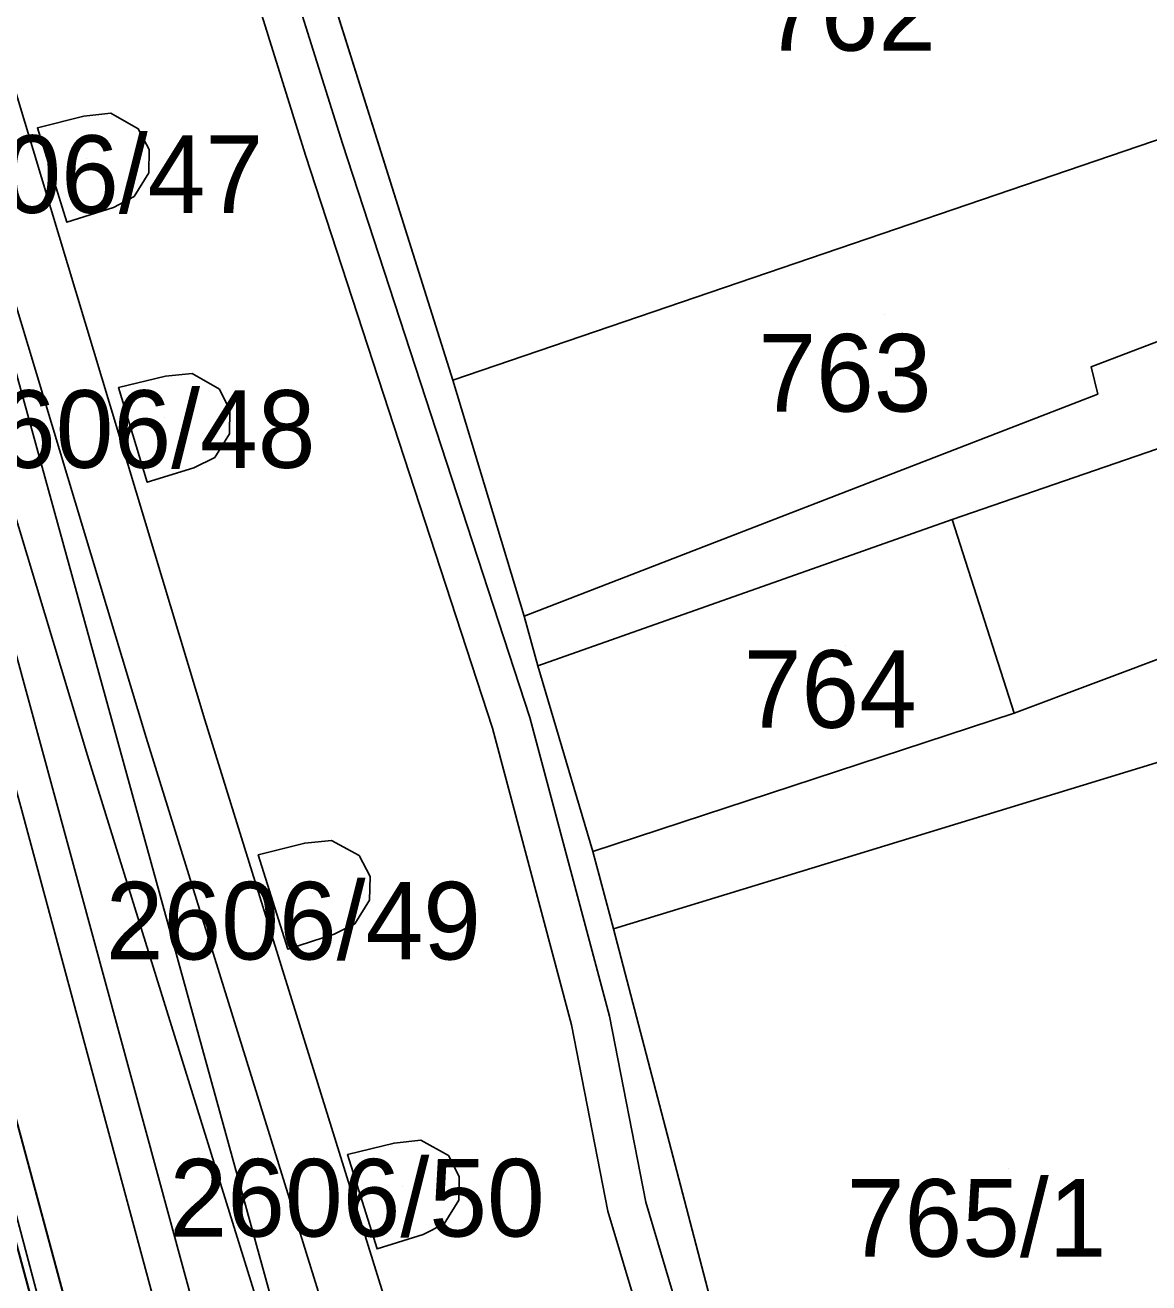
# Model space of a CAD drawing. Extents: x -263423 to -261326, y -1240067 to -1237864.
# Drawn here: x -262913.52 to -262884.56, y -1239127.34 to -1239094.93 of the extents above; entities that cross this region are included whole.
import ezdxf

# ---------------------------------------------------------------- set-up
doc = ezdxf.new("R2010")
doc.units = 0
for name, color, linetype in [('body_kn', 7, 'Continuous'), ('kladpar_druhypozemkov', 7, 'Continuous'), ('kladpar_hranice', 7, 'Continuous'), ('kladpar_parcelnecisla', 7, 'Continuous'), ('kladpar_plochy', 7, 'Continuous'), ('tarchy_linie', 7, 'Continuous'), ('zappar_hrandruhpozemk', 7, 'Continuous')]:
    doc.layers.add(name, color=color, linetype=linetype)

msp = doc.modelspace()

# ---------------------------------------------------------------- linework, layer by layer
at = {"layer": 'body_kn'}
for p, q in [((-262912, -1239097.28), (-262912, -1239097.28)), ((-262911.31, -1239097.2), (-262911.31, -1239097.2)), ((-262913.2, -1239097.58), (-262913.2, -1239097.58)), ((-262913.2, -1239097.58), (-262913.2, -1239097.58)), ((-262910.6, -1239097.6), (-262910.6, -1239097.6)), ((-262910.32, -1239098.14), (-262910.32, -1239098.14)), ((-262906.29, -1239098.28), (-262906.29, -1239098.28)), ((-262905.34, -1239097.98), (-262905.34, -1239097.98)), ((-262910.33, -1239098.74), (-262910.33, -1239098.74)), ((-262910.71, -1239099.35), (-262910.71, -1239099.35)), ((-262911.24, -1239099.63), (-262911.24, -1239099.63)), ((-262912.44, -1239100.01), (-262912.44, -1239100.01)), ((-262886.05, -1239103.74), (-262886.05, -1239103.74)), ((-262909.9, -1239103.98), (-262909.9, -1239103.98)), ((-262909.21, -1239103.91), (-262909.21, -1239103.91)), ((-262902.5, -1239104.08), (-262902.5, -1239104.08)), ((-262911.11, -1239104.27), (-262911.11, -1239104.27)), ((-262911.11, -1239104.27), (-262911.11, -1239104.27)), ((-262908.51, -1239104.31), (-262908.51, -1239104.31)), ((-262885.88, -1239104.44), (-262885.88, -1239104.44)), ((-262908.24, -1239104.85), (-262908.24, -1239104.85)), ((-262908.25, -1239105.46), (-262908.25, -1239105.46)), ((-262909.17, -1239106.34), (-262909.17, -1239106.34)), ((-262908.63, -1239106.07), (-262908.63, -1239106.07)), ((-262910.37, -1239106.71), (-262910.37, -1239106.71)), ((-262889.63, -1239107.67), (-262889.63, -1239107.67)), ((-262900.66, -1239110.16), (-262900.66, -1239110.16)), ((-262900.31, -1239111.44), (-262900.31, -1239111.44)), ((-262908.89, -1239112.83), (-262908.89, -1239112.83)), ((-262900.51, -1239112.77), (-262900.51, -1239112.77)), ((-262888.03, -1239112.66), (-262888.03, -1239112.66)), ((-262888.03, -1239112.66), (-262888.03, -1239112.66)), ((-262901.47, -1239113.05), (-262901.47, -1239113.05)), ((-262910.4, -1239113.29), (-262910.4, -1239113.29)), ((-262911.91, -1239113.75), (-262911.91, -1239113.75)), ((-262906.31, -1239116.01), (-262906.31, -1239116.01)), ((-262905.62, -1239115.94), (-262905.62, -1239115.94)), ((-262907.51, -1239116.31), (-262907.51, -1239116.31)), ((-262907.51, -1239116.31), (-262907.51, -1239116.31)), ((-262904.91, -1239116.33), (-262904.91, -1239116.33)), ((-262898.89, -1239116.23), (-262898.89, -1239116.23)), ((-262898.89, -1239116.23), (-262898.89, -1239116.23)), ((-262904.63, -1239116.87), (-262904.63, -1239116.87)), ((-262904.64, -1239117.48), (-262904.64, -1239117.48)), ((-262905.55, -1239118.36), (-262905.55, -1239118.36)), ((-262905.02, -1239118.09), (-262905.02, -1239118.09)), ((-262898.36, -1239118.22), (-262898.36, -1239118.22)), ((-262906.75, -1239118.74), (-262906.75, -1239118.74)), ((-262898.46, -1239120.47), (-262898.46, -1239120.47)), ((-262899.44, -1239120.69), (-262899.44, -1239120.69)), ((-262904.01, -1239123.74), (-262904.01, -1239123.74)), ((-262903.32, -1239123.67), (-262903.32, -1239123.67)), ((-262905.21, -1239124.04), (-262905.21, -1239124.04)), ((-262905.21, -1239124.04), (-262905.21, -1239124.04)), ((-262902.61, -1239124.06), (-262902.61, -1239124.06)), ((-262902.33, -1239124.6), (-262902.33, -1239124.6)), ((-262902.34, -1239125.21), (-262902.34, -1239125.21)), ((-262898.5, -1239125.5), (-262898.5, -1239125.5)), ((-262897.52, -1239125.26), (-262897.52, -1239125.26)), ((-262902.72, -1239125.82), (-262902.72, -1239125.82)), ((-262903.26, -1239126.1), (-262903.26, -1239126.1)), ((-262904.45, -1239126.47), (-262904.45, -1239126.47))]:
    msp.add_line(p, q, dxfattribs=at)
at = {"layer": 'kladpar_druhypozemkov'}
for p, q in [((-262911.94, -1239098.36), (-262911.94, -1239098.36)), ((-262891.37, -1239102.39), (-262891.37, -1239102.39)), ((-262909.92, -1239105.03), (-262909.92, -1239105.03)), ((-262892.38, -1239110.93), (-262892.38, -1239110.93)), ((-262906.11, -1239117.31), (-262906.11, -1239117.31)), ((-262888.17, -1239124.39), (-262888.17, -1239124.39)), ((-262903.79, -1239124.87), (-262903.79, -1239124.87))]:
    msp.add_line(p, q, dxfattribs=at)
at = {"layer": 'kladpar_hranice'}
for points in [[(-262893.7, -1239198.54), (-262894.26, -1239197.51), (-262894.85, -1239196.01), (-262897, -1239188.23), (-262908.38, -1239146.15), (-262916.07, -1239117.75), (-262916.78, -1239116.26), (-262916.91, -1239114.53), (-262935.33, -1239046.71)], [(-262935.33, -1239046.71), (-262916.91, -1239114.53), (-262916.78, -1239116.26), (-262916.07, -1239117.75), (-262908.38, -1239146.15), (-262897, -1239188.23), (-262894.85, -1239196.01), (-262894.26, -1239197.51), (-262893.7, -1239198.54)], [(-262934.53, -1239046.57), (-262916.13, -1239114.22), (-262915.54, -1239115.96), (-262915.28, -1239117.47), (-262907.62, -1239145.83), (-262896.2, -1239187.94), (-262894.08, -1239195.84), (-262893.54, -1239197.19), (-262892.9, -1239198.44)], [(-262882.09, -1239085.08), (-262863.43, -1239079.26), (-262845.68, -1239073.99), (-262839.87, -1239072.34), (-262840.28, -1239070.93), (-262817.72, -1239063.42), (-262815.92, -1239068.28), (-262804.92, -1239064.46), (-262804.22, -1239064.15), (-262802.54, -1239068.64), (-262803.43, -1239068.94), (-262812.96, -1239072.03), (-262826.95, -1239076.56), (-262867.57, -1239091.24), (-262877.82, -1239095.66), (-262902.5, -1239104.08), (-262905.88, -1239093.33), (-262882.09, -1239085.08)], [(-262877.82, -1239095.66), (-262867.57, -1239091.24), (-262826.95, -1239076.56), (-262824.67, -1239082.26), (-262830.49, -1239084.62), (-262845.67, -1239091.15), (-262842.8, -1239099.09), (-262852.59, -1239102.56), (-262855.47, -1239095), (-262865.58, -1239099.04), (-262877.68, -1239103.86), (-262880.24, -1239104.88), (-262880.42, -1239104.5), (-262889.63, -1239107.67), (-262900.31, -1239111.44), (-262900.66, -1239110.16), (-262902.5, -1239104.08), (-262877.82, -1239095.66)], [(-262905.88, -1239093.33), (-262902.5, -1239104.08), (-262900.66, -1239110.16), (-262900.31, -1239111.44), (-262898.89, -1239116.23), (-262898.36, -1239118.22), (-262892.33, -1239141.29), (-262882.82, -1239170.53)], [(-262880.42, -1239104.5), (-262880.24, -1239104.88), (-262877.68, -1239103.86), (-262865.58, -1239099.04), (-262855.47, -1239095), (-262852.59, -1239102.56), (-262877.47, -1239111.62), (-262884.37, -1239113.94), (-262898.36, -1239118.22), (-262898.89, -1239116.23), (-262900.31, -1239111.44), (-262889.63, -1239107.67), (-262880.42, -1239104.5)], [(-262913.2, -1239097.58), (-262912, -1239097.28), (-262911.31, -1239097.2), (-262910.6, -1239097.6), (-262910.32, -1239098.14), (-262910.33, -1239098.74), (-262910.71, -1239099.35), (-262911.24, -1239099.63), (-262912.44, -1239100.01), (-262913.2, -1239097.58)], [(-262912, -1239097.28), (-262913.2, -1239097.58), (-262912.44, -1239100.01), (-262911.24, -1239099.63), (-262910.71, -1239099.35), (-262910.33, -1239098.74), (-262910.32, -1239098.14), (-262910.6, -1239097.6), (-262911.31, -1239097.2), (-262912, -1239097.28)], [(-262822.99, -1239113.06), (-262828.11, -1239114.91), (-262830.61, -1239115.81), (-262830.86, -1239115.87), (-262834.7, -1239117.31), (-262838.92, -1239118.87), (-262842.78, -1239109.77), (-262854.56, -1239114.01), (-262883.4, -1239124.39), (-262882.63, -1239126.82), (-262879.24, -1239125.88), (-262878.23, -1239129.07), (-262875.93, -1239128.36), (-262874.04, -1239134.82), (-262892.33, -1239141.29), (-262898.36, -1239118.22), (-262884.37, -1239113.94), (-262877.47, -1239111.62), (-262852.59, -1239102.56)], [(-262911.11, -1239104.27), (-262909.9, -1239103.98), (-262909.21, -1239103.91), (-262908.51, -1239104.31), (-262908.24, -1239104.85), (-262908.25, -1239105.46), (-262908.63, -1239106.07), (-262909.17, -1239106.34), (-262910.37, -1239106.71), (-262911.11, -1239104.27)], [(-262909.9, -1239103.98), (-262911.11, -1239104.27), (-262910.37, -1239106.71), (-262909.17, -1239106.34), (-262908.63, -1239106.07), (-262908.25, -1239105.46), (-262908.24, -1239104.85), (-262908.51, -1239104.31), (-262909.21, -1239103.91), (-262909.9, -1239103.98)], [(-262892.9, -1239198.44), (-262893.54, -1239197.19), (-262894.08, -1239195.84), (-262896.2, -1239187.94), (-262907.62, -1239145.83), (-262915.28, -1239117.47), (-262915.54, -1239115.96), (-262916.13, -1239114.22)], [(-262907.51, -1239116.31), (-262906.31, -1239116.01), (-262905.62, -1239115.94), (-262904.91, -1239116.33), (-262904.63, -1239116.87), (-262904.64, -1239117.48), (-262905.02, -1239118.09), (-262905.55, -1239118.36), (-262906.75, -1239118.74), (-262907.51, -1239116.31)], [(-262906.31, -1239116.01), (-262907.51, -1239116.31), (-262906.75, -1239118.74), (-262905.55, -1239118.36), (-262905.02, -1239118.09), (-262904.64, -1239117.48), (-262904.63, -1239116.87), (-262904.91, -1239116.33), (-262905.62, -1239115.94), (-262906.31, -1239116.01)], [(-262905.21, -1239124.04), (-262904.01, -1239123.74), (-262903.32, -1239123.67), (-262902.61, -1239124.06), (-262902.33, -1239124.6), (-262902.34, -1239125.21), (-262902.72, -1239125.82), (-262903.26, -1239126.1), (-262904.45, -1239126.47), (-262905.21, -1239124.04)], [(-262904.01, -1239123.74), (-262905.21, -1239124.04), (-262904.45, -1239126.47), (-262903.26, -1239126.1), (-262902.72, -1239125.82), (-262902.34, -1239125.21), (-262902.33, -1239124.6), (-262902.61, -1239124.06), (-262903.32, -1239123.67), (-262904.01, -1239123.74)]]:
    msp.add_lwpolyline(points, dxfattribs=at)
at = {"layer": 'kladpar_plochy'}
for p, q in [((-262905.88, -1239093.33), (-262902.5, -1239104.08)), ((-262912, -1239097.28), (-262913.2, -1239097.58)), ((-262911.31, -1239097.2), (-262912, -1239097.28)), ((-262910.6, -1239097.6), (-262911.31, -1239097.2)), ((-262913.2, -1239097.58), (-262912.44, -1239100.01)), ((-262910.32, -1239098.14), (-262910.6, -1239097.6)), ((-262910.33, -1239098.74), (-262910.32, -1239098.14)), ((-262910.71, -1239099.35), (-262910.33, -1239098.74)), ((-262911.24, -1239099.63), (-262910.71, -1239099.35)), ((-262912.44, -1239100.01), (-262911.24, -1239099.63)), ((-262909.9, -1239103.98), (-262911.11, -1239104.27)), ((-262909.21, -1239103.91), (-262909.9, -1239103.98)), ((-262908.51, -1239104.31), (-262909.21, -1239103.91)), ((-262902.5, -1239104.08), (-262900.66, -1239110.16)), ((-262911.11, -1239104.27), (-262910.37, -1239106.71)), ((-262908.24, -1239104.85), (-262908.51, -1239104.31)), ((-262908.25, -1239105.46), (-262908.24, -1239104.85)), ((-262908.63, -1239106.07), (-262908.25, -1239105.46)), ((-262910.37, -1239106.71), (-262909.17, -1239106.34)), ((-262909.17, -1239106.34), (-262908.63, -1239106.07)), ((-262900.66, -1239110.16), (-262900.31, -1239111.44)), ((-262900.31, -1239111.44), (-262898.89, -1239116.23)), ((-262906.31, -1239116.01), (-262907.51, -1239116.31)), ((-262905.62, -1239115.94), (-262906.31, -1239116.01)), ((-262904.91, -1239116.33), (-262905.62, -1239115.94)), ((-262907.51, -1239116.31), (-262906.75, -1239118.74)), ((-262904.63, -1239116.87), (-262904.91, -1239116.33)), ((-262898.89, -1239116.23), (-262898.36, -1239118.22)), ((-262904.64, -1239117.48), (-262904.63, -1239116.87)), ((-262907.62, -1239145.83), (-262915.28, -1239117.47)), ((-262905.02, -1239118.09), (-262904.64, -1239117.48)), ((-262916.07, -1239117.75), (-262908.38, -1239146.15)), ((-262906.75, -1239118.74), (-262905.55, -1239118.36)), ((-262905.55, -1239118.36), (-262905.02, -1239118.09)), ((-262898.36, -1239118.22), (-262892.33, -1239141.29)), ((-262904.01, -1239123.74), (-262905.21, -1239124.04)), ((-262903.32, -1239123.67), (-262904.01, -1239123.74)), ((-262902.61, -1239124.06), (-262903.32, -1239123.67)), ((-262905.21, -1239124.04), (-262904.45, -1239126.47)), ((-262902.33, -1239124.6), (-262902.61, -1239124.06)), ((-262902.34, -1239125.21), (-262902.33, -1239124.6)), ((-262902.72, -1239125.82), (-262902.34, -1239125.21)), ((-262903.26, -1239126.1), (-262902.72, -1239125.82)), ((-262904.45, -1239126.47), (-262903.26, -1239126.1))]:
    msp.add_line(p, q, dxfattribs=at)
for points in [[(-262893.7, -1239198.54), (-262894.26, -1239197.51), (-262894.85, -1239196.01), (-262897, -1239188.23), (-262908.38, -1239146.15), (-262916.07, -1239117.75), (-262916.78, -1239116.26), (-262916.91, -1239114.53), (-262935.33, -1239046.71)], [(-262934.53, -1239046.57), (-262916.13, -1239114.22), (-262915.54, -1239115.96), (-262915.28, -1239117.47), (-262907.62, -1239145.83), (-262896.2, -1239187.94), (-262894.08, -1239195.84), (-262893.54, -1239197.19), (-262892.9, -1239198.44)], [(-262822.99, -1239113.06), (-262828.11, -1239114.91), (-262830.61, -1239115.81), (-262830.86, -1239115.87), (-262834.7, -1239117.31), (-262838.92, -1239118.87), (-262842.78, -1239109.77), (-262854.56, -1239114.01), (-262883.4, -1239124.39), (-262882.63, -1239126.82), (-262879.24, -1239125.88), (-262878.23, -1239129.07), (-262875.93, -1239128.36), (-262874.04, -1239134.82), (-262892.33, -1239141.29), (-262898.36, -1239118.22), (-262884.37, -1239113.94), (-262877.47, -1239111.62), (-262852.59, -1239102.56), (-262842.8, -1239099.09), (-262845.67, -1239091.15)]]:
    msp.add_lwpolyline(points, dxfattribs=at)
for points in [[(-262882.09, -1239085.08), (-262863.43, -1239079.26), (-262845.68, -1239073.99), (-262839.87, -1239072.34), (-262840.28, -1239070.93), (-262817.72, -1239063.42), (-262815.92, -1239068.28), (-262804.92, -1239064.46), (-262804.22, -1239064.15), (-262802.54, -1239068.64), (-262803.43, -1239068.94), (-262812.96, -1239072.03), (-262826.95, -1239076.56), (-262867.57, -1239091.24), (-262877.82, -1239095.66), (-262902.5, -1239104.08), (-262905.88, -1239093.33)], [(-262877.82, -1239095.66), (-262867.57, -1239091.24), (-262826.95, -1239076.56), (-262824.67, -1239082.26), (-262830.49, -1239084.62), (-262845.67, -1239091.15), (-262842.8, -1239099.09), (-262852.59, -1239102.56), (-262855.47, -1239095), (-262865.58, -1239099.04), (-262877.68, -1239103.86), (-262880.24, -1239104.88), (-262880.42, -1239104.5), (-262889.63, -1239107.67), (-262900.31, -1239111.44), (-262900.66, -1239110.16), (-262902.5, -1239104.08)], [(-262880.42, -1239104.5), (-262880.24, -1239104.88), (-262877.68, -1239103.86), (-262865.58, -1239099.04), (-262855.47, -1239095), (-262852.59, -1239102.56), (-262877.47, -1239111.62), (-262884.37, -1239113.94), (-262898.36, -1239118.22), (-262898.89, -1239116.23), (-262900.31, -1239111.44), (-262889.63, -1239107.67)], [(-262913.2, -1239097.58), (-262912, -1239097.28), (-262911.31, -1239097.2), (-262910.6, -1239097.6), (-262910.32, -1239098.14), (-262910.33, -1239098.74), (-262910.71, -1239099.35), (-262911.24, -1239099.63), (-262912.44, -1239100.01)], [(-262911.11, -1239104.27), (-262909.9, -1239103.98), (-262909.21, -1239103.91), (-262908.51, -1239104.31), (-262908.24, -1239104.85), (-262908.25, -1239105.46), (-262908.63, -1239106.07), (-262909.17, -1239106.34), (-262910.37, -1239106.71)], [(-262907.51, -1239116.31), (-262906.31, -1239116.01), (-262905.62, -1239115.94), (-262904.91, -1239116.33), (-262904.63, -1239116.87), (-262904.64, -1239117.48), (-262905.02, -1239118.09), (-262905.55, -1239118.36), (-262906.75, -1239118.74)], [(-262905.21, -1239124.04), (-262904.01, -1239123.74), (-262903.32, -1239123.67), (-262902.61, -1239124.06), (-262902.33, -1239124.6), (-262902.34, -1239125.21), (-262902.72, -1239125.82), (-262903.26, -1239126.1), (-262904.45, -1239126.47)]]:
    msp.add_lwpolyline(points, close=True, dxfattribs=at)
at = {"layer": 'tarchy_linie'}
for points in [[(-263002.97, -1238844.59), (-262980.25, -1238906.63), (-262945.58, -1239009.09), (-262938.29, -1239035.86), (-262916.38, -1239115.82), (-262894.12, -1239198.57), (-262876.1, -1239267.26), (-262891.06, -1239270.91), (-262884.2, -1239310.37), (-262877, -1239350.49), (-262869.73, -1239390.34), (-262861.27, -1239427.46), (-262857.92, -1239442.13), (-262856.51, -1239448.31), (-262843.28, -1239506.14), (-262818.17, -1239595.69)], [(-262939.39, -1239021.15), (-262934.2, -1239037.72), (-262927.16, -1239063.69), (-262920.98, -1239083.65), (-262911.91, -1239113.75), (-262904.59, -1239137.31), (-262894.43, -1239170.66), (-262879.54, -1239218.96), (-262874.31, -1239236.62), (-262867.48, -1239260.06), (-262865.11, -1239267.42), (-262873.73, -1239264.88), (-262891.31, -1239197.83), (-262913.63, -1239115.08), (-262935.59, -1239035.12), (-262939.39, -1239021.15)], [(-262917.96, -1239082.73), (-262908.89, -1239112.83), (-262901.57, -1239136.39), (-262891.41, -1239169.74), (-262881.41, -1239202.19)], [(-262919.47, -1239083.19), (-262910.4, -1239113.29), (-262903.08, -1239136.85), (-262892.92, -1239170.2), (-262878.03, -1239218.5), (-262872.8, -1239236.18), (-262865.97, -1239259.6), (-262862.37, -1239270.8), (-262860.78, -1239275.15), (-262855.16, -1239281.3), (-262847.42, -1239296.93), (-262841.21, -1239314.37), (-262837.3, -1239325.72), (-262833.82, -1239334.62), (-262823.57, -1239363.35), (-262812.24, -1239393.87)], [(-262875.25, -1239204.22), (-262878.13, -1239194.18), (-262881.79, -1239181.12), (-262883.72, -1239175.9), (-262885.46, -1239169.27), (-262887.48, -1239161.88), (-262890.05, -1239154.51), (-262891.22, -1239150.24), (-262894.24, -1239140.37), (-262896.89, -1239130.89), (-262898.5, -1239125.5), (-262899.44, -1239120.69), (-262901.47, -1239113.05), (-262906.29, -1239098.28), (-262908.22, -1239092.11)], [(-262907.27, -1239091.82), (-262905.34, -1239097.98), (-262900.51, -1239112.77), (-262898.46, -1239120.47), (-262897.52, -1239125.26), (-262895.93, -1239130.61), (-262893.28, -1239140.09), (-262890.26, -1239149.97), (-262889.09, -1239154.21), (-262886.53, -1239161.58), (-262884.49, -1239169.01), (-262882.76, -1239175.6), (-262880.84, -1239180.81), (-262877.17, -1239193.9), (-262874.23, -1239204.17)], [(-262905.88, -1239093.33), (-262902.5, -1239104.08), (-262900.66, -1239110.16), (-262900.31, -1239111.44), (-262898.89, -1239116.23), (-262898.36, -1239118.22), (-262892.33, -1239141.29), (-262884.21, -1239166.27), (-262883.53, -1239168.75), (-262883.01, -1239170.73), (-262883.41, -1239171.16), (-262882.73, -1239171.87), (-262881.81, -1239175.3), (-262879.89, -1239180.5), (-262877.08, -1239190.49), (-262876.47, -1239192.68), (-262876.04, -1239192.57), (-262874.05, -1239193.56), (-262875.22, -1239194.02), (-262876.94, -1239194.62), (-262873.93, -1239204.53)]]:
    msp.add_lwpolyline(points, dxfattribs=at)
at = {"layer": 'zappar_hrandruhpozemk'}
for p, q in [((-262888.03, -1239112.66), (-262889.63, -1239107.67)), ((-262878.24, -1239108.99), (-262888.03, -1239112.66)), ((-262898.89, -1239116.23), (-262888.03, -1239112.66))]:
    msp.add_line(p, q, dxfattribs=at)
for points in [[(-262937.97, -1239016.31), (-262934.66, -1239027.99), (-262902.52, -1239144.64), (-262891.29, -1239186.07), (-262888.2, -1239197.19), (-262878.19, -1239233.56), (-262876.42, -1239236.1)], [(-262936.28, -1239028.36), (-262904.5, -1239145.15), (-262893.25, -1239186.79)], [(-262878.5, -1239100.86), (-262886.05, -1239103.74), (-262885.88, -1239104.44), (-262900.66, -1239110.16)]]:
    msp.add_lwpolyline(points, dxfattribs=at)

# ---------------------------------------------------------------- texts
at = {"layer": 'kladpar_parcelnecisla'}
for s, p in [('762', (-262894.508, -1239095.59)), ('2606/47', (-262917.052, -1239099.77)), ('763', (-262894.624, -1239104.89)), ('2606/48', (-262915.703, -1239106.34)), ('764', (-262895.002, -1239113.04)), ('2606/49', (-262911.439, -1239119.01)), ('2606/50', (-262909.796, -1239126.15)), ('765/1', (-262892.347, -1239126.67))]:
    msp.add_text(s, height=2, dxfattribs=at).set_placement(p)

doc.saveas('drawing.dxf')
